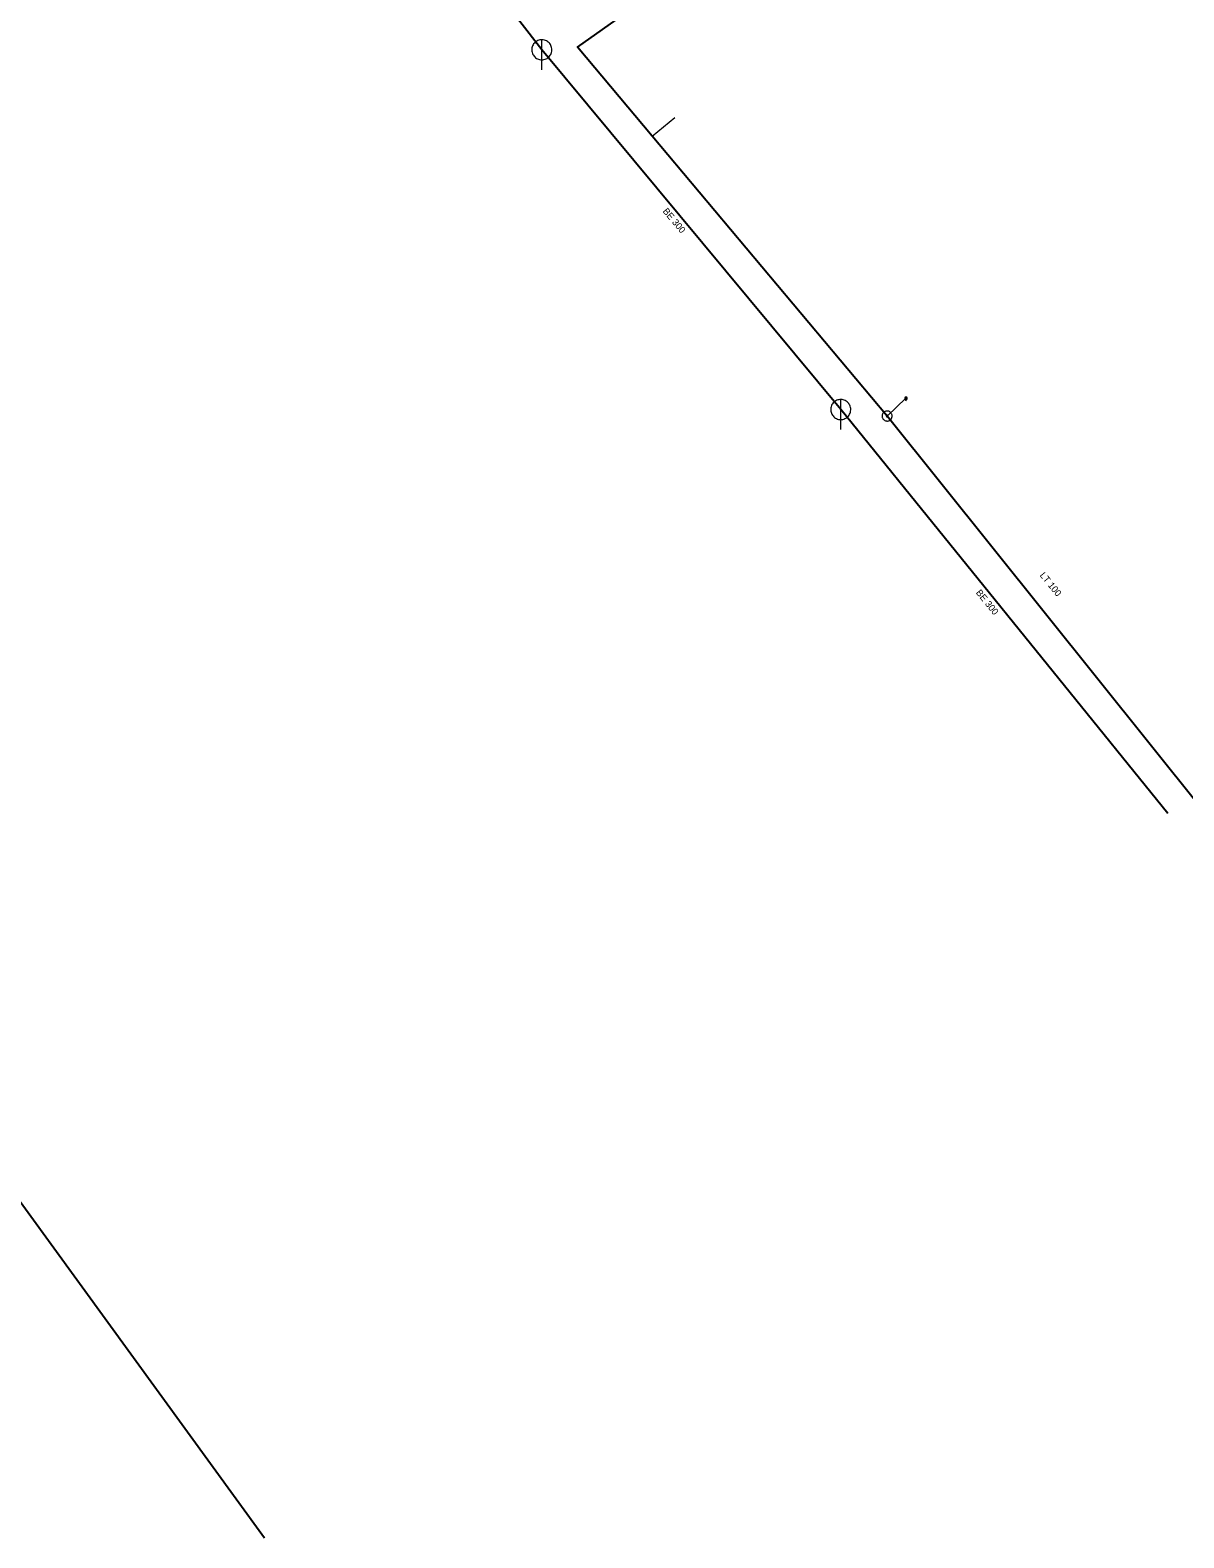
# Model space of a CAD drawing. Extents: x -688296 to -687852, y -973332 to -972816.
# Drawn here: x -688073 to -687958, y -973331.6 to -973181.4 of the extents above; entities that cross this region are included whole.
import ezdxf
from ezdxf.enums import TextEntityAlignment as Align

# ---------------------------------------------------------------- set-up
doc = ezdxf.new("R2010")
doc.units = 0
doc.header["$LTSCALE"] = 0.27
for name, color, linetype, lineweight in [('1', 7, 'Continuous', 25), ('13', 7, 'Continuous', 13), ('14', 7, 'Continuous', 13), ('17', 7, 'Continuous', 25), ('22', 7, 'Continuous', 13), ('47', 7, 'Continuous', 13), ('9', 7, 'Continuous', 13)]:
    doc.layers.add(name, color=color, linetype=linetype, lineweight=lineweight)

msp = doc.modelspace()

# ---------------------------------------------------------------- linework, layer by layer
at = {"layer": '13'}
msp.add_line((-688011.001, -973191.963), (-688008.726, -973190.096), dxfattribs=at)
at = {"layer": '14', "lineweight": 25}
for p, q in [((-688021.994, -973183.349), (-688026.221, -973177.902)), ((-687992.195, -973219.204), (-688021.993, -973183.349)), ((-687959.572, -973259.458), (-687992.195, -973219.204))]:
    msp.add_line(p, q, dxfattribs=at)
at = {"layer": '14'}
msp.add_line((-687987.568, -973219.849), (-687985.688, -973218.079), dxfattribs=at)
at = {"layer": '17'}
msp.add_line((-687956.115, -973259.105), (-687987.568, -973219.849), dxfattribs=at)
for points in [[(-688123.609, -972815.609), (-688135.91, -972839.761), (-688146.524, -972867.704), (-688149.164, -972878.87), (-688150.368, -972974.473), (-688134.778, -973051.136), (-688125.903, -973068.701), (-688203.651, -973132.27), (-688148.612, -973199.748), (-688078.631, -973291.807), (-688049.631, -973331.642)], [(-687987.568, -973219.849), (-688011, -973191.963), (-688018.429, -973183.079), (-687972.436, -973150.573)]]:
    msp.add_lwpolyline(points, dxfattribs=at)
at = {"layer": '22'}
for p, q in [((-688021.994, -973185.349), (-688021.993, -973182.349)), ((-687992.195, -973221.204), (-687992.194, -973218.204))]:
    msp.add_line(p, q, dxfattribs=at)
for points in [[(-688020.994, -973183.349), (-688020.999, -973183.24), (-688021.017, -973183.132), (-688021.047, -973183.026), (-688021.087, -973182.925), (-688021.139, -973182.828), (-688021.201, -973182.738), (-688021.273, -973182.655), (-688021.353, -973182.581), (-688021.441, -973182.515), (-688021.535, -973182.46), (-688021.635, -973182.415), (-688021.74, -973182.382), (-688021.847, -973182.36), (-688021.956, -973182.35), (-688022.066, -973182.352), (-688022.174, -973182.366), (-688022.281, -973182.391), (-688022.384, -973182.428), (-688022.482, -973182.477), (-688022.574, -973182.535), (-688022.66, -973182.604), (-688022.737, -973182.681), (-688022.806, -973182.767), (-688022.865, -973182.859), (-688022.913, -973182.957), (-688022.95, -973183.06), (-688022.976, -973183.167), (-688022.99, -973183.275), (-688022.993, -973183.385), (-688022.983, -973183.494), (-688022.962, -973183.601), (-688022.928, -973183.705), (-688022.884, -973183.805), (-688022.829, -973183.9), (-688022.763, -973183.988), (-688022.689, -973184.068), (-688022.606, -973184.14), (-688022.516, -973184.202), (-688022.42, -973184.254), (-688022.318, -973184.295), (-688022.213, -973184.325), (-688022.105, -973184.343), (-688021.995, -973184.349), (-688021.886, -973184.343), (-688021.778, -973184.325), (-688021.673, -973184.296), (-688021.571, -973184.255), (-688021.474, -973184.203), (-688021.384, -973184.141), (-688021.301, -973184.07), (-688021.226, -973183.99), (-688021.161, -973183.902), (-688021.105, -973183.808), (-688021.061, -973183.708), (-688021.027, -973183.604), (-688021.005, -973183.496), (-688020.995, -973183.387)], [(-687991.195, -973219.204), (-687991.2, -973219.095), (-687991.218, -973218.987), (-687991.248, -973218.881), (-687991.288, -973218.78), (-687991.34, -973218.683), (-687991.402, -973218.593), (-687991.474, -973218.51), (-687991.554, -973218.436), (-687991.642, -973218.37), (-687991.736, -973218.315), (-687991.836, -973218.27), (-687991.941, -973218.237), (-687992.048, -973218.215), (-687992.157, -973218.205), (-687992.267, -973218.207), (-687992.375, -973218.221), (-687992.482, -973218.246), (-687992.585, -973218.283), (-687992.683, -973218.332), (-687992.775, -973218.39), (-687992.861, -973218.459), (-687992.938, -973218.536), (-687993.007, -973218.622), (-687993.066, -973218.714), (-687993.114, -973218.812), (-687993.151, -973218.915), (-687993.177, -973219.022), (-687993.191, -973219.13), (-687993.194, -973219.24), (-687993.184, -973219.349), (-687993.163, -973219.456), (-687993.129, -973219.56), (-687993.085, -973219.66), (-687993.03, -973219.755), (-687992.964, -973219.843), (-687992.89, -973219.923), (-687992.807, -973219.995), (-687992.717, -973220.057), (-687992.621, -973220.109), (-687992.519, -973220.15), (-687992.414, -973220.18), (-687992.306, -973220.198), (-687992.196, -973220.204), (-687992.087, -973220.198), (-687991.979, -973220.18), (-687991.874, -973220.151), (-687991.772, -973220.11), (-687991.675, -973220.058), (-687991.585, -973219.996), (-687991.502, -973219.925), (-687991.427, -973219.845), (-687991.362, -973219.757), (-687991.306, -973219.663), (-687991.262, -973219.563), (-687991.228, -973219.459), (-687991.206, -973219.351), (-687991.196, -973219.242)]]:
    msp.add_lwpolyline(points, close=True, dxfattribs=at)
at = {"layer": '47'}
for points in [[(-687987.246, -973220.231), (-687987.208, -973220.196), (-687987.173, -973220.156), (-687987.144, -973220.113), (-687987.118, -973220.068), (-687987.098, -973220.019), (-687987.083, -973219.969), (-687987.073, -973219.918), (-687987.069, -973219.866), (-687987.069, -973219.814), (-687987.075, -973219.762), (-687987.087, -973219.71), (-687987.105, -973219.661), (-687987.126, -973219.614), (-687987.153, -973219.569), (-687987.185, -973219.527), (-687987.22, -973219.489), (-687987.26, -973219.454), (-687987.303, -973219.424), (-687987.348, -973219.399), (-687987.397, -973219.379), (-687987.447, -973219.364), (-687987.499, -973219.353), (-687987.551, -973219.349), (-687987.603, -973219.349), (-687987.654, -973219.356), (-687987.706, -973219.368), (-687987.756, -973219.385), (-687987.802, -973219.407), (-687987.847, -973219.434), (-687987.889, -973219.466), (-687987.927, -973219.501), (-687987.962, -973219.541), (-687987.992, -973219.584), (-687988.017, -973219.629), (-687988.037, -973219.678), (-687988.053, -973219.727), (-687988.063, -973219.779), (-687988.068, -973219.831), (-687988.067, -973219.884), (-687988.06, -973219.935), (-687988.048, -973219.987), (-687988.032, -973220.036), (-687988.009, -973220.083), (-687987.982, -973220.128), (-687987.95, -973220.17), (-687987.915, -973220.208), (-687987.875, -973220.243), (-687987.833, -973220.272), (-687987.787, -973220.298), (-687987.738, -973220.318), (-687987.689, -973220.334), (-687987.638, -973220.343), (-687987.586, -973220.348), (-687987.533, -973220.347), (-687987.481, -973220.341), (-687987.429, -973220.329), (-687987.381, -973220.312), (-687987.333, -973220.29), (-687987.288, -973220.263)], [(-687987.515, -973219.911), (-687987.508, -973219.906), (-687987.503, -973219.899), (-687987.498, -973219.892), (-687987.494, -973219.885), (-687987.49, -973219.877), (-687987.488, -973219.868), (-687987.486, -973219.86), (-687987.485, -973219.851), (-687987.486, -973219.843), (-687987.487, -973219.834), (-687987.489, -973219.826), (-687987.492, -973219.818), (-687987.495, -973219.81), (-687987.499, -973219.803), (-687987.505, -973219.796), (-687987.51, -973219.789), (-687987.517, -973219.784), (-687987.524, -973219.779), (-687987.531, -973219.775), (-687987.539, -973219.771), (-687987.548, -973219.769), (-687987.556, -973219.767), (-687987.565, -973219.766), (-687987.574, -973219.766), (-687987.582, -973219.768), (-687987.59, -973219.77), (-687987.598, -973219.773), (-687987.606, -973219.776), (-687987.613, -973219.78), (-687987.62, -973219.786), (-687987.627, -973219.791), (-687987.632, -973219.798), (-687987.637, -973219.805), (-687987.641, -973219.812), (-687987.645, -973219.82), (-687987.647, -973219.828), (-687987.649, -973219.837), (-687987.65, -973219.846), (-687987.65, -973219.855), (-687987.648, -973219.863), (-687987.646, -973219.871), (-687987.643, -973219.879), (-687987.64, -973219.887), (-687987.636, -973219.894), (-687987.63, -973219.901), (-687987.625, -973219.908), (-687987.618, -973219.913), (-687987.611, -973219.918), (-687987.604, -973219.922), (-687987.596, -973219.926), (-687987.588, -973219.928), (-687987.579, -973219.93), (-687987.57, -973219.931), (-687987.562, -973219.93), (-687987.553, -973219.929), (-687987.545, -973219.927), (-687987.537, -973219.924), (-687987.529, -973219.921), (-687987.522, -973219.917)]]:
    msp.add_lwpolyline(points, close=True, dxfattribs=at)
at = {"layer": '9'}
msp.add_line((-687985.689, -973218.206), (-687985.689, -973218.331), dxfattribs=at)
for points in [[(-687985.815, -973218.078), (-687985.814, -973218.091), (-687985.812, -973218.104), (-687985.809, -973218.117), (-687985.804, -973218.129), (-687985.798, -973218.141), (-687985.791, -973218.152), (-687985.783, -973218.162), (-687985.773, -973218.172), (-687985.763, -973218.18), (-687985.752, -973218.187), (-687985.74, -973218.193), (-687985.728, -973218.198), (-687985.715, -973218.201), (-687985.702, -973218.203), (-687985.689, -973218.206), (-687985.676, -973218.205), (-687985.663, -973218.203), (-687985.65, -973218.2), (-687985.638, -973218.195), (-687985.626, -973218.189), (-687985.615, -973218.182), (-687985.605, -973218.174), (-687985.595, -973218.164), (-687985.587, -973218.154), (-687985.58, -973218.143), (-687985.574, -973218.131), (-687985.569, -973218.119), (-687985.566, -973218.106), (-687985.564, -973218.093), (-687985.562, -973218.08), (-687985.563, -973218.067), (-687985.565, -973218.054), (-687985.568, -973218.041), (-687985.573, -973218.029), (-687985.579, -973218.017), (-687985.586, -973218.006), (-687985.594, -973217.996), (-687985.604, -973217.986), (-687985.614, -973217.978), (-687985.625, -973217.971), (-687985.637, -973217.965), (-687985.649, -973217.96), (-687985.662, -973217.957), (-687985.675, -973217.955), (-687985.688, -973217.953), (-687985.701, -973217.953), (-687985.714, -973217.955), (-687985.727, -973217.958), (-687985.739, -973217.963), (-687985.751, -973217.969), (-687985.762, -973217.976), (-687985.772, -973217.984), (-687985.782, -973217.994), (-687985.79, -973218.004), (-687985.797, -973218.015), (-687985.803, -973218.027), (-687985.808, -973218.039), (-687985.811, -973218.052), (-687985.813, -973218.065)], [(-687985.795, -973218.078), (-687985.795, -973218.089), (-687985.793, -973218.1), (-687985.79, -973218.111), (-687985.786, -973218.121), (-687985.781, -973218.131), (-687985.775, -973218.14), (-687985.768, -973218.149), (-687985.76, -973218.157), (-687985.751, -973218.164), (-687985.742, -973218.17), (-687985.732, -973218.175), (-687985.722, -973218.179), (-687985.711, -973218.182), (-687985.7, -973218.184), (-687985.689, -973218.184), (-687985.678, -973218.186), (-687985.667, -973218.184), (-687985.656, -973218.181), (-687985.646, -973218.177), (-687985.636, -973218.172), (-687985.627, -973218.166), (-687985.618, -973218.159), (-687985.61, -973218.151), (-687985.603, -973218.142), (-687985.597, -973218.133), (-687985.592, -973218.123), (-687985.588, -973218.113), (-687985.585, -973218.102), (-687985.583, -973218.091), (-687985.582, -973218.08), (-687985.582, -973218.069), (-687985.584, -973218.058), (-687985.587, -973218.047), (-687985.591, -973218.037), (-687985.596, -973218.027), (-687985.602, -973218.018), (-687985.609, -973218.009), (-687985.617, -973218.001), (-687985.626, -973217.994), (-687985.635, -973217.988), (-687985.645, -973217.983), (-687985.655, -973217.979), (-687985.666, -973217.976), (-687985.677, -973217.974), (-687985.688, -973217.973), (-687985.699, -973217.972), (-687985.71, -973217.974), (-687985.721, -973217.977), (-687985.731, -973217.981), (-687985.741, -973217.986), (-687985.75, -973217.992), (-687985.759, -973217.999), (-687985.767, -973218.007), (-687985.774, -973218.016), (-687985.78, -973218.025), (-687985.785, -973218.035), (-687985.789, -973218.045), (-687985.792, -973218.056), (-687985.794, -973218.067)], [(-687985.776, -973218.078), (-687985.775, -973218.087), (-687985.774, -973218.096), (-687985.771, -973218.105), (-687985.768, -973218.113), (-687985.764, -973218.121), (-687985.759, -973218.129), (-687985.753, -973218.136), (-687985.747, -973218.142), (-687985.74, -973218.148), (-687985.732, -973218.153), (-687985.724, -973218.157), (-687985.716, -973218.16), (-687985.707, -973218.163), (-687985.698, -973218.164), (-687985.689, -973218.167), (-687985.68, -973218.166), (-687985.671, -973218.165), (-687985.662, -973218.162), (-687985.654, -973218.159), (-687985.646, -973218.155), (-687985.638, -973218.15), (-687985.631, -973218.144), (-687985.625, -973218.138), (-687985.619, -973218.131), (-687985.614, -973218.123), (-687985.61, -973218.115), (-687985.607, -973218.107), (-687985.604, -973218.098), (-687985.603, -973218.089), (-687985.601, -973218.08), (-687985.602, -973218.071), (-687985.603, -973218.062), (-687985.606, -973218.053), (-687985.609, -973218.045), (-687985.613, -973218.037), (-687985.618, -973218.029), (-687985.624, -973218.022), (-687985.63, -973218.016), (-687985.637, -973218.01), (-687985.645, -973218.005), (-687985.653, -973218.001), (-687985.661, -973217.998), (-687985.67, -973217.995), (-687985.679, -973217.994), (-687985.688, -973217.992), (-687985.697, -973217.992), (-687985.706, -973217.993), (-687985.715, -973217.996), (-687985.723, -973217.999), (-687985.731, -973218.003), (-687985.739, -973218.008), (-687985.746, -973218.014), (-687985.752, -973218.02), (-687985.758, -973218.027), (-687985.763, -973218.035), (-687985.767, -973218.043), (-687985.77, -973218.051), (-687985.773, -973218.06), (-687985.774, -973218.069)], [(-687985.756, -973218.078), (-687985.756, -973218.085), (-687985.754, -973218.092), (-687985.753, -973218.099), (-687985.75, -973218.105), (-687985.747, -973218.111), (-687985.743, -973218.117), (-687985.739, -973218.123), (-687985.734, -973218.128), (-687985.728, -973218.132), (-687985.722, -973218.136), (-687985.716, -973218.139), (-687985.71, -973218.142), (-687985.703, -973218.143), (-687985.696, -973218.145), (-687985.689, -973218.146), (-687985.682, -973218.147), (-687985.675, -973218.145), (-687985.668, -973218.144), (-687985.662, -973218.141), (-687985.655, -973218.138), (-687985.65, -973218.134), (-687985.644, -973218.13), (-687985.639, -973218.125), (-687985.635, -973218.119), (-687985.631, -973218.113), (-687985.628, -973218.107), (-687985.625, -973218.101), (-687985.623, -973218.094), (-687985.622, -973218.087), (-687985.621, -973218.08), (-687985.621, -973218.073), (-687985.622, -973218.066), (-687985.624, -973218.059), (-687985.627, -973218.053), (-687985.63, -973218.046), (-687985.634, -973218.041), (-687985.638, -973218.035), (-687985.643, -973218.03), (-687985.649, -973218.026), (-687985.654, -973218.022), (-687985.661, -973218.019), (-687985.667, -973218.016), (-687985.674, -973218.014), (-687985.681, -973218.013), (-687985.688, -973218.012), (-687985.695, -973218.011), (-687985.702, -973218.012), (-687985.709, -973218.014), (-687985.715, -973218.017), (-687985.721, -973218.02), (-687985.727, -973218.024), (-687985.733, -973218.028), (-687985.738, -973218.033), (-687985.742, -973218.039), (-687985.746, -973218.044), (-687985.749, -973218.051), (-687985.752, -973218.057), (-687985.753, -973218.064), (-687985.755, -973218.071)], [(-687985.736, -973218.078), (-687985.736, -973218.083), (-687985.735, -973218.088), (-687985.734, -973218.093), (-687985.732, -973218.097), (-687985.73, -973218.102), (-687985.727, -973218.106), (-687985.724, -973218.109), (-687985.72, -973218.113), (-687985.717, -973218.116), (-687985.713, -973218.119), (-687985.708, -973218.121), (-687985.704, -973218.123), (-687985.699, -973218.124), (-687985.694, -973218.125), (-687985.689, -973218.125), (-687985.684, -973218.127), (-687985.679, -973218.126), (-687985.674, -973218.125), (-687985.67, -973218.123), (-687985.665, -973218.121), (-687985.661, -973218.118), (-687985.657, -973218.115), (-687985.654, -973218.111), (-687985.651, -973218.108), (-687985.648, -973218.104), (-687985.646, -973218.099), (-687985.644, -973218.095), (-687985.643, -973218.09), (-687985.642, -973218.085), (-687985.642, -973218.08), (-687985.641, -973218.075), (-687985.642, -973218.07), (-687985.643, -973218.065), (-687985.645, -973218.061), (-687985.647, -973218.056), (-687985.65, -973218.052), (-687985.653, -973218.048), (-687985.656, -973218.045), (-687985.66, -973218.042), (-687985.664, -973218.039), (-687985.669, -973218.037), (-687985.673, -973218.035), (-687985.678, -973218.034), (-687985.683, -973218.033), (-687985.688, -973218.032), (-687985.693, -973218.031), (-687985.698, -973218.032), (-687985.703, -973218.033), (-687985.707, -973218.035), (-687985.712, -973218.037), (-687985.716, -973218.04), (-687985.719, -973218.043), (-687985.723, -973218.046), (-687985.726, -973218.05), (-687985.729, -973218.054), (-687985.731, -973218.059), (-687985.733, -973218.063), (-687985.734, -973218.068), (-687985.735, -973218.073)], [(-687985.716, -973218.078), (-687985.716, -973218.081), (-687985.716, -973218.084), (-687985.715, -973218.086), (-687985.714, -973218.089), (-687985.713, -973218.092), (-687985.711, -973218.094), (-687985.709, -973218.096), (-687985.707, -973218.098), (-687985.705, -973218.1), (-687985.703, -973218.102), (-687985.7, -973218.103), (-687985.697, -973218.104), (-687985.695, -973218.105), (-687985.692, -973218.105), (-687985.689, -973218.105), (-687985.686, -973218.107), (-687985.683, -973218.107), (-687985.68, -973218.106), (-687985.678, -973218.105), (-687985.675, -973218.104), (-687985.673, -973218.102), (-687985.67, -973218.1), (-687985.668, -973218.098), (-687985.667, -973218.096), (-687985.665, -973218.094), (-687985.664, -973218.091), (-687985.663, -973218.088), (-687985.662, -973218.086), (-687985.662, -973218.083), (-687985.66, -973218.08), (-687985.661, -973218.077), (-687985.661, -973218.074), (-687985.662, -973218.071), (-687985.663, -973218.069), (-687985.664, -973218.066), (-687985.666, -973218.064), (-687985.667, -973218.061), (-687985.669, -973218.059), (-687985.672, -973218.058), (-687985.674, -973218.056), (-687985.677, -973218.055), (-687985.679, -973218.054), (-687985.682, -973218.053), (-687985.685, -973218.053), (-687985.688, -973218.051), (-687985.691, -973218.051), (-687985.694, -973218.051), (-687985.696, -973218.052), (-687985.699, -973218.053), (-687985.702, -973218.054), (-687985.704, -973218.056), (-687985.706, -973218.057), (-687985.708, -973218.059), (-687985.71, -973218.062), (-687985.712, -973218.064), (-687985.713, -973218.067), (-687985.714, -973218.069), (-687985.715, -973218.072), (-687985.715, -973218.075)], [(-687985.697, -973218.078), (-687985.697, -973218.079), (-687985.697, -973218.08), (-687985.696, -973218.08), (-687985.696, -973218.081), (-687985.696, -973218.082), (-687985.695, -973218.083), (-687985.695, -973218.083), (-687985.694, -973218.084), (-687985.694, -973218.084), (-687985.693, -973218.085), (-687985.692, -973218.085), (-687985.691, -973218.085), (-687985.691, -973218.086), (-687985.69, -973218.087), (-687985.689, -973218.087), (-687985.688, -973218.087), (-687985.687, -973218.087), (-687985.687, -973218.087), (-687985.686, -973218.087), (-687985.685, -973218.087), (-687985.684, -973218.086), (-687985.684, -973218.086), (-687985.683, -973218.085), (-687985.683, -973218.085), (-687985.682, -973218.084), (-687985.682, -973218.083), (-687985.681, -973218.082), (-687985.681, -973218.082), (-687985.681, -973218.081), (-687985.68, -973218.08), (-687985.68, -973218.079), (-687985.68, -973218.078), (-687985.68, -973218.078), (-687985.681, -973218.077), (-687985.681, -973218.076), (-687985.682, -973218.075), (-687985.682, -973218.075), (-687985.683, -973218.074), (-687985.683, -973218.074), (-687985.684, -973218.073), (-687985.685, -973218.073), (-687985.686, -973218.072), (-687985.686, -973218.072), (-687985.687, -973218.072), (-687985.688, -973218.071), (-687985.689, -973218.071), (-687985.69, -973218.07), (-687985.69, -973218.07), (-687985.691, -973218.071), (-687985.692, -973218.071), (-687985.693, -973218.072), (-687985.693, -973218.072), (-687985.694, -973218.073), (-687985.694, -973218.073), (-687985.695, -973218.074), (-687985.695, -973218.075), (-687985.695, -973218.076), (-687985.696, -973218.076), (-687985.696, -973218.077)]]:
    msp.add_lwpolyline(points, close=True, dxfattribs=at)
msp.add_lwpolyline([(-687985.658, -973218.297), (-687985.689, -973218.331), (-687985.72, -973218.295)], dxfattribs=at)

# ---------------------------------------------------------------- texts
at = {"layer": '1'}
for s, rotation, p in [('BE 300', 310, (-688009.0469, -973200.5805)), ('BE 300', 310, (-688009.0469, -973200.5805)), ('BE 300', 310, (-688009.0469, -973200.5805)), ('BE 300', 310, (-688009.0469, -973200.5805)), ('BE 300', 310, (-688009.0469, -973200.5805)), ('LT 100', 309, (-687971.5214, -973236.8152)), ('LT 100', 309, (-687971.5214, -973236.8152)), ('LT 100', 309, (-687971.5214, -973236.8152)), ('LT 100', 309, (-687971.5214, -973236.8152)), ('LT 100', 309, (-687971.5214, -973236.8152)), ('BE 300', 309, (-687977.8417, -973238.6048)), ('BE 300', 309, (-687977.8417, -973238.6048)), ('BE 300', 309, (-687977.8417, -973238.6048)), ('BE 300', 309, (-687977.8417, -973238.6048)), ('BE 300', 309, (-687977.8417, -973238.6048))]:
    msp.add_text(s, height=0.6667, rotation=rotation, dxfattribs=at).set_placement(p, align=Align.CENTER)

doc.saveas('drawing.dxf')
